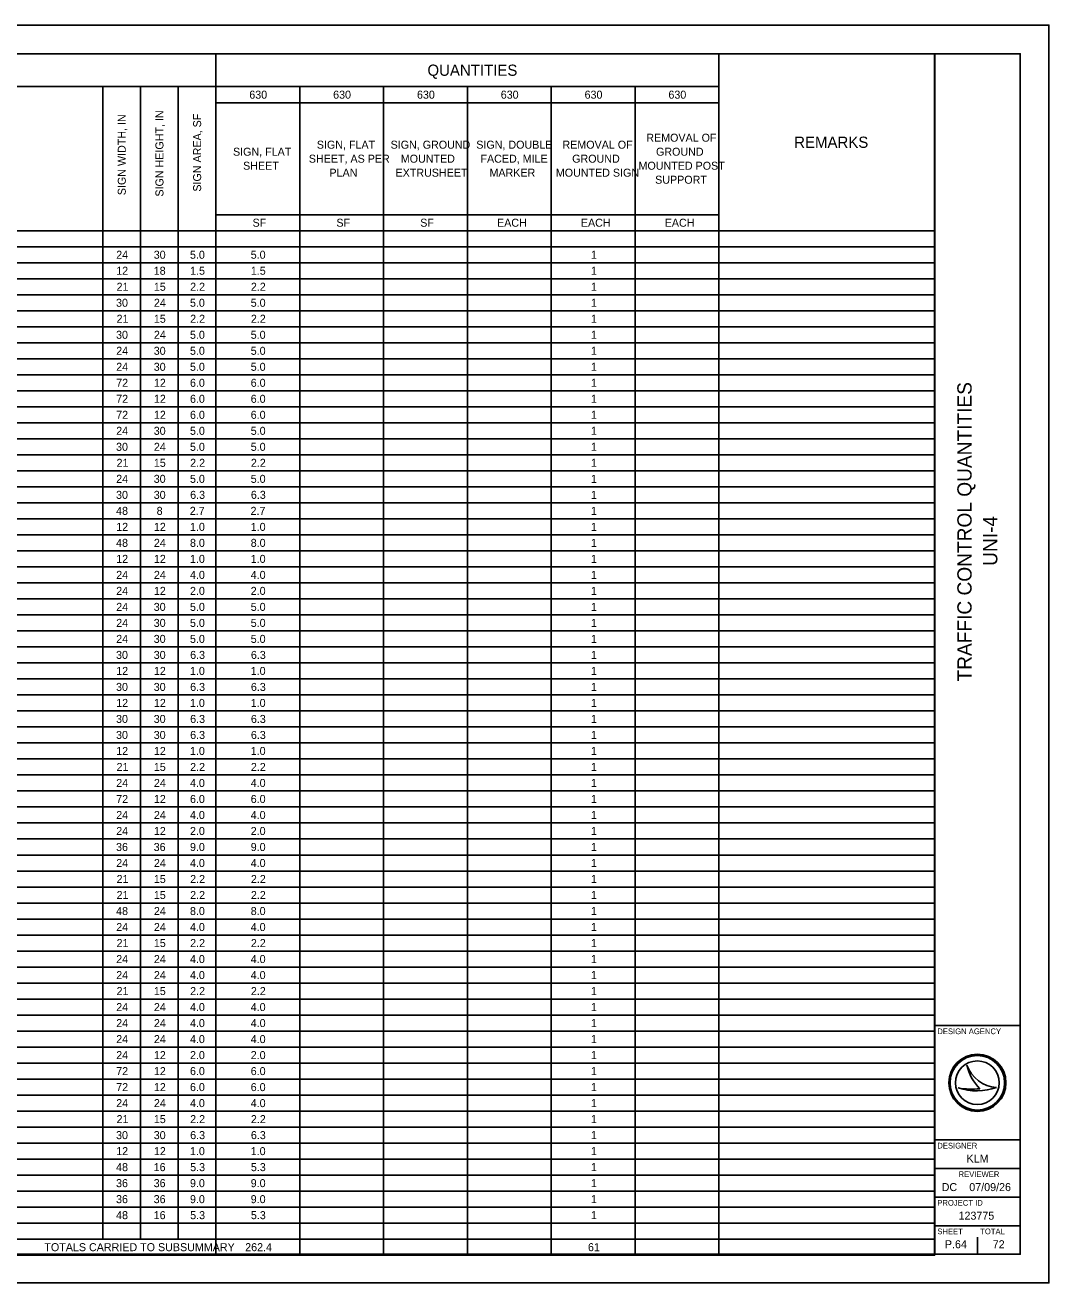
# Model space of a CAD drawing. Extents: x 0 to 34, y 0 to 22.
# Drawn here: x 16.1 to 34, y 0 to 22 of the extents above; entities that cross this region are included whole.
import ezdxf

# ---------------------------------------------------------------- set-up
doc = ezdxf.new("R2010")
doc.units = 0
for name, color, linetype in [('SH_Border', 7, 'Continuous'), ('SH_Cut_Line', 7, 'Continuous'), ('SH_Data', 7, 'Continuous'), ('SH_Text', 7, 'Continuous')]:
    doc.layers.add(name, color=color, linetype=linetype)

msp = doc.modelspace()

# ---------------------------------------------------------------- linework, layer by layer
at = {"layer": 'SH_Border'}
for p, q in [((32, 0.5), (32, 21.5)), ((32, 4.5), (33.5, 4.5)), ((32, 2.5), (33.5, 2.5)), ((32, 2), (33.5, 2)), ((32, 1.5), (33.5, 1.5)), ((32, 1), (33.5, 1))]:
    msp.add_line(p, q, dxfattribs=at)
msp.add_lwpolyline([(1.5, 21.5), (33.5, 21.5), (33.5, 0.5), (1.5, 0.5)], close=True, dxfattribs=at)
at = {"layer": 'SH_Cut_Line'}
msp.add_lwpolyline([(0, 0), (34, 0), (34, 22), (0, 22)], close=True, dxfattribs=at)
at = {"layer": 'SH_Data'}
for p, q in [((1.5, 21.5), (32.004, 21.5)), ((19.436, 21.5), (19.436, 0.484)), ((28.232, 21.5), (28.232, 0.484)), ((32.004, 21.5), (32.004, 0.484)), ((1.5, 20.924), (28.232, 20.924)), ((17.46, 20.924), (17.46, 0.764)), ((18.119, 20.924), (18.119, 0.764)), ((18.778, 20.924), (18.778, 0.764)), ((20.902, 20.924), (20.902, 0.484)), ((22.368, 20.924), (22.368, 0.484)), ((23.834, 20.924), (23.834, 0.484)), ((25.3, 20.924), (25.3, 0.484)), ((26.766, 20.924), (26.766, 0.484)), ((19.436, 20.644), (28.232, 20.644)), ((19.436, 18.684), (28.232, 18.684)), ((1.5, 18.404), (32.004, 18.404)), ((1.5, 18.124), (32.004, 18.124)), ((1.5, 17.844), (32.004, 17.844)), ((1.5, 17.564), (32.004, 17.564)), ((1.5, 17.284), (32.004, 17.284)), ((1.5, 17.004), (32.004, 17.004)), ((1.5, 16.724), (32.004, 16.724)), ((1.5, 16.444), (32.004, 16.444)), ((1.5, 16.164), (32.004, 16.164)), ((1.5, 15.884), (32.004, 15.884)), ((1.5, 15.604), (32.004, 15.604)), ((1.5, 15.324), (32.004, 15.324)), ((1.5, 15.044), (32.004, 15.044)), ((1.5, 14.764), (32.004, 14.764)), ((1.5, 14.484), (32.004, 14.484)), ((1.5, 14.204), (32.004, 14.204)), ((1.5, 13.924), (32.004, 13.924)), ((1.5, 13.644), (32.004, 13.644)), ((1.5, 13.364), (32.004, 13.364)), ((1.5, 13.084), (32.004, 13.084)), ((1.5, 12.804), (32.004, 12.804)), ((1.5, 12.524), (32.004, 12.524)), ((1.5, 12.244), (32.004, 12.244)), ((1.5, 11.964), (32.004, 11.964)), ((1.5, 11.684), (32.004, 11.684)), ((1.5, 11.404), (32.004, 11.404)), ((1.5, 11.124), (32.004, 11.124)), ((1.5, 10.844), (32.004, 10.844)), ((1.5, 10.564), (32.004, 10.564)), ((1.5, 10.284), (32.004, 10.284)), ((1.5, 10.004), (32.004, 10.004)), ((1.5, 9.724), (32.004, 9.724)), ((1.5, 9.444), (32.004, 9.444)), ((1.5, 9.164), (32.004, 9.164)), ((1.5, 8.884), (32.004, 8.884)), ((1.5, 8.604), (32.004, 8.604)), ((1.5, 8.324), (32.004, 8.324)), ((1.5, 8.044), (32.004, 8.044)), ((1.5, 7.764), (32.004, 7.764)), ((1.5, 7.484), (32.004, 7.484)), ((1.5, 7.204), (32.004, 7.204)), ((1.5, 6.924), (32.004, 6.924)), ((1.5, 6.644), (32.004, 6.644)), ((1.5, 6.364), (32.004, 6.364)), ((1.5, 6.084), (32.004, 6.084)), ((1.5, 5.804), (32.004, 5.804)), ((1.5, 5.524), (32.004, 5.524)), ((1.5, 5.244), (32.004, 5.244)), ((1.5, 4.964), (32.004, 4.964)), ((1.5, 4.684), (32.004, 4.684)), ((1.5, 4.404), (32.004, 4.404)), ((1.5, 4.124), (32.004, 4.124)), ((1.5, 3.844), (32.004, 3.844)), ((32.567, 3.81), (32.567, 3.81)), ((1.5, 3.564), (32.004, 3.564)), ((32.417, 3.41), (32.417, 3.41)), ((32.75, 3.5), (32.75, 3.5)), ((33.087, 3.419), (33.087, 3.419)), ((1.5, 3.284), (32.004, 3.284)), ((1.5, 3.004), (32.004, 3.004)), ((1.5, 2.724), (32.004, 2.724)), ((1.5, 2.444), (32.004, 2.444)), ((1.5, 2.164), (32.004, 2.164)), ((1.5, 1.884), (32.004, 1.884)), ((1.5, 1.604), (32.004, 1.604)), ((1.5, 1.324), (32.004, 1.324)), ((1.5, 1.044), (32.004, 1.044)), ((1.5, 0.764), (32.004, 0.764)), ((32.375, 0.675), (32.375, 0.675)), ((32.75, 0.5), (32.75, 0.8)), ((1.5, 0.484), (32.004, 0.484))]:
    msp.add_line(p, q, dxfattribs=at)
for radius in [0.5, 0.477, 0.477, 0.382]:
    msp.add_circle((32.75, 3.5), radius, dxfattribs=at)
for centre, radius, start, end in [((33.116, 3.998), 0.58, 198.9257, 198.9319), ((33.347, 3.97), 0.796, 191.6379, 191.6421), ((33.116, 3.998), 0.58, 198.9319, 267.1657), ((33.347, 3.97), 0.796, 191.6421, 226.0947), ((32.739, 4.37), 1.013, 251.4576, 290.0832), ((32.648, 4.654), 1.266, 259.4964, 259.4995), ((32.739, 4.37), 1.013, 251.4527, 251.4576), ((32.648, 4.654), 1.266, 259.4995, 276.6672)]:
    msp.add_arc(centre, radius, start, end, dxfattribs=at)

# ---------------------------------------------------------------- texts
for s, p in [('TRAFFIC CONTROL QUANTITIES', (32.65, 10.519)), ('UNI-4', (33.1, 12.542))]:
    msp.add_text(s, height=0.25, rotation=90, dxfattribs=at).set_placement(p)
for s, height, p in [('DESIGN AGENCY', 0.1, (32.05, 4.35)), ('DESIGNER', 0.1, (32.05, 2.35)), ('KLM', 0.14, (32.561, 2.105)), ('REVIEWER', 0.1, (32.422, 1.85)), ('DC', 0.14, (32.126, 1.605)), ('07/09/26', 0.14, (32.609, 1.605)), ('PROJECT ID', 0.1, (32.05, 1.35)), ('123775', 0.14, (32.421, 1.105)), ('SHEET', 0.1, (32.05, 0.85)), ('TOTAL', 0.1, (32.8, 0.85)), ('P.64', 0.14, (32.182, 0.605)), ('72', 0.14, (33.019, 0.605))]:
    msp.add_text(s, height=height, dxfattribs=at).set_placement(p)
at = {"layer": 'SH_Text'}
for s, height, p in [('QUANTITIES', 0.196, (23.134, 21.114)), ('630', 0.14, (20.019, 20.714)), ('630', 0.14, (21.485, 20.714)), ('630', 0.14, (22.951, 20.714)), ('630', 0.14, (24.416, 20.714)), ('630', 0.14, (25.882, 20.714)), ('630', 0.14, (27.348, 20.714)), ('REMOVAL OF ', 0.14, (26.961, 19.961)), ('REMARKS', 0.196, (29.547, 19.854)), ('SIGN, FLAT ', 0.14, (19.734, 19.716)), ('SIGN, FLAT ', 0.14, (21.2, 19.839)), ('SIGN, GROUND ', 0.14, (22.49, 19.839)), ('SIGN, DOUBLE ', 0.14, (23.988, 19.839)), ('REMOVAL OF ', 0.14, (25.495, 19.839)), ('GROUND ', 0.14, (27.131, 19.716)), ('SHEET', 0.14, (19.911, 19.471)), ('SHEET, AS PER ', 0.14, (21.06, 19.594)), ('MOUNTED ', 0.14, (22.668, 19.594)), ('FACED, MILE ', 0.14, (24.061, 19.594)), ('GROUND ', 0.14, (25.665, 19.594)), ('MOUNTED POST ', 0.14, (26.825, 19.471)), ('PLAN', 0.14, (21.421, 19.349)), ('EXTRUSHEET', 0.14, (22.576, 19.349)), ('MARKER', 0.14, (24.219, 19.349)), ('MOUNTED SIGN', 0.14, (25.379, 19.349)), ('SUPPORT', 0.14, (27.116, 19.226)), ('SF', 0.14, (20.076, 18.474)), ('SF', 0.14, (21.542, 18.474)), ('SF', 0.14, (23.008, 18.474)), ('EACH', 0.14, (24.351, 18.474)), ('EACH', 0.14, (25.817, 18.474)), ('EACH', 0.14, (27.283, 18.474)), ('24', 0.14, (17.692, 17.914)), ('30', 0.14, (18.348, 17.914)), ('5.0', 0.14, (18.982, 17.914)), ('5.0', 0.14, (20.044, 17.914)), ('1', 0.14, (25.992, 17.914)), ('12', 0.14, (17.692, 17.634)), ('18', 0.14, (18.348, 17.634)), ('1.5', 0.14, (18.984, 17.634)), ('1.5', 0.14, (20.046, 17.634)), ('1', 0.14, (25.992, 17.634)), ('21', 0.14, (17.698, 17.354)), ('15', 0.14, (18.35, 17.354)), ('2.2', 0.14, (18.985, 17.354)), ('2.2', 0.14, (20.047, 17.354)), ('1', 0.14, (25.992, 17.354)), ('30', 0.14, (17.689, 17.074)), ('24', 0.14, (18.351, 17.074)), ('5.0', 0.14, (18.982, 17.074)), ('5.0', 0.14, (20.044, 17.074)), ('1', 0.14, (25.992, 17.074)), ('21', 0.14, (17.698, 16.794)), ('15', 0.14, (18.35, 16.794)), ('2.2', 0.14, (18.985, 16.794)), ('2.2', 0.14, (20.047, 16.794)), ('1', 0.14, (25.992, 16.794)), ('30', 0.14, (17.689, 16.514)), ('24', 0.14, (18.351, 16.514)), ('5.0', 0.14, (18.982, 16.514)), ('5.0', 0.14, (20.044, 16.514)), ('1', 0.14, (25.992, 16.514)), ('24', 0.14, (17.692, 16.234)), ('30', 0.14, (18.348, 16.234)), ('5.0', 0.14, (18.982, 16.234)), ('5.0', 0.14, (20.044, 16.234)), ('1', 0.14, (25.992, 16.234)), ('24', 0.14, (17.692, 15.954)), ('30', 0.14, (18.348, 15.954)), ('5.0', 0.14, (18.982, 15.954)), ('5.0', 0.14, (20.044, 15.954)), ('1', 0.14, (25.992, 15.954)), ('72', 0.14, (17.692, 15.674)), ('12', 0.14, (18.351, 15.674)), ('6.0', 0.14, (18.982, 15.674)), ('6.0', 0.14, (20.044, 15.674)), ('1', 0.14, (25.992, 15.674)), ('72', 0.14, (17.692, 15.394)), ('12', 0.14, (18.351, 15.394)), ('6.0', 0.14, (18.982, 15.394)), ('6.0', 0.14, (20.044, 15.394)), ('1', 0.14, (25.992, 15.394)), ('72', 0.14, (17.692, 15.114)), ('12', 0.14, (18.351, 15.114)), ('6.0', 0.14, (18.982, 15.114)), ('6.0', 0.14, (20.044, 15.114)), ('1', 0.14, (25.992, 15.114)), ('24', 0.14, (17.692, 14.834)), ('30', 0.14, (18.348, 14.834)), ('5.0', 0.14, (18.982, 14.834)), ('5.0', 0.14, (20.044, 14.834)), ('1', 0.14, (25.992, 14.834)), ('30', 0.14, (17.689, 14.554)), ('24', 0.14, (18.351, 14.554)), ('5.0', 0.14, (18.982, 14.554)), ('5.0', 0.14, (20.044, 14.554)), ('1', 0.14, (25.992, 14.554)), ('21', 0.14, (17.698, 14.274)), ('15', 0.14, (18.35, 14.274)), ('2.2', 0.14, (18.985, 14.274)), ('2.2', 0.14, (20.047, 14.274)), ('1', 0.14, (25.992, 14.274)), ('24', 0.14, (17.692, 13.994)), ('30', 0.14, (18.348, 13.994)), ('5.0', 0.14, (18.982, 13.994)), ('5.0', 0.14, (20.044, 13.994)), ('1', 0.14, (25.992, 13.994)), ('30', 0.14, (17.689, 13.714)), ('30', 0.14, (18.348, 13.714)), ('6.3', 0.14, (18.985, 13.714)), ('6.3', 0.14, (20.047, 13.714)), ('1', 0.14, (25.992, 13.714)), ('48', 0.14, (17.69, 13.434)), ('8', 0.14, (18.399, 13.434)), ('2.7', 0.14, (18.979, 13.434)), ('2.7', 0.14, (20.041, 13.434)), ('1', 0.14, (25.992, 13.434)), ('12', 0.14, (17.692, 13.154)), ('12', 0.14, (18.351, 13.154)), ('1.0', 0.14, (18.982, 13.154)), ('1.0', 0.14, (20.044, 13.154)), ('1', 0.14, (25.992, 13.154)), ('48', 0.14, (17.69, 12.874)), ('24', 0.14, (18.351, 12.874)), ('8.0', 0.14, (18.982, 12.874)), ('8.0', 0.14, (20.044, 12.874)), ('1', 0.14, (25.992, 12.874)), ('12', 0.14, (17.692, 12.594)), ('12', 0.14, (18.351, 12.594)), ('1.0', 0.14, (18.982, 12.594)), ('1.0', 0.14, (20.044, 12.594)), ('1', 0.14, (25.992, 12.594)), ('24', 0.14, (17.692, 12.314)), ('24', 0.14, (18.351, 12.314)), ('4.0', 0.14, (18.982, 12.314)), ('4.0', 0.14, (20.044, 12.314)), ('1', 0.14, (25.992, 12.314)), ('24', 0.14, (17.692, 12.034)), ('12', 0.14, (18.351, 12.034)), ('2.0', 0.14, (18.982, 12.034)), ('2.0', 0.14, (20.044, 12.034)), ('1', 0.14, (25.992, 12.034)), ('24', 0.14, (17.692, 11.754)), ('30', 0.14, (18.348, 11.754)), ('5.0', 0.14, (18.982, 11.754)), ('5.0', 0.14, (20.044, 11.754)), ('1', 0.14, (25.992, 11.754)), ('24', 0.14, (17.692, 11.474)), ('30', 0.14, (18.348, 11.474)), ('5.0', 0.14, (18.982, 11.474)), ('5.0', 0.14, (20.044, 11.474)), ('1', 0.14, (25.992, 11.474)), ('24', 0.14, (17.692, 11.194)), ('30', 0.14, (18.348, 11.194)), ('5.0', 0.14, (18.982, 11.194)), ('5.0', 0.14, (20.044, 11.194)), ('1', 0.14, (25.992, 11.194)), ('30', 0.14, (17.689, 10.914)), ('30', 0.14, (18.348, 10.914)), ('6.3', 0.14, (18.985, 10.914)), ('6.3', 0.14, (20.047, 10.914)), ('1', 0.14, (25.992, 10.914)), ('12', 0.14, (17.692, 10.634)), ('12', 0.14, (18.351, 10.634)), ('1.0', 0.14, (18.982, 10.634)), ('1.0', 0.14, (20.044, 10.634)), ('1', 0.14, (25.992, 10.634)), ('30', 0.14, (17.689, 10.354)), ('30', 0.14, (18.348, 10.354)), ('6.3', 0.14, (18.985, 10.354)), ('6.3', 0.14, (20.047, 10.354)), ('1', 0.14, (25.992, 10.354)), ('12', 0.14, (17.692, 10.074)), ('12', 0.14, (18.351, 10.074)), ('1.0', 0.14, (18.982, 10.074)), ('1.0', 0.14, (20.044, 10.074)), ('1', 0.14, (25.992, 10.074)), ('30', 0.14, (17.689, 9.794)), ('30', 0.14, (18.348, 9.794)), ('6.3', 0.14, (18.985, 9.794)), ('6.3', 0.14, (20.047, 9.794)), ('1', 0.14, (25.992, 9.794)), ('30', 0.14, (17.689, 9.514)), ('30', 0.14, (18.348, 9.514)), ('6.3', 0.14, (18.985, 9.514)), ('6.3', 0.14, (20.047, 9.514)), ('1', 0.14, (25.992, 9.514)), ('12', 0.14, (17.692, 9.234)), ('12', 0.14, (18.351, 9.234)), ('1.0', 0.14, (18.982, 9.234)), ('1.0', 0.14, (20.044, 9.234)), ('1', 0.14, (25.992, 9.234)), ('21', 0.14, (17.698, 8.954)), ('15', 0.14, (18.35, 8.954)), ('2.2', 0.14, (18.985, 8.954)), ('2.2', 0.14, (20.047, 8.954)), ('1', 0.14, (25.992, 8.954)), ('24', 0.14, (17.692, 8.674)), ('24', 0.14, (18.351, 8.674)), ('4.0', 0.14, (18.982, 8.674)), ('4.0', 0.14, (20.044, 8.674)), ('1', 0.14, (25.992, 8.674)), ('72', 0.14, (17.692, 8.394)), ('12', 0.14, (18.351, 8.394)), ('6.0', 0.14, (18.982, 8.394)), ('6.0', 0.14, (20.044, 8.394)), ('1', 0.14, (25.992, 8.394)), ('24', 0.14, (17.692, 8.114)), ('24', 0.14, (18.351, 8.114)), ('4.0', 0.14, (18.982, 8.114)), ('4.0', 0.14, (20.044, 8.114)), ('1', 0.14, (25.992, 8.114)), ('24', 0.14, (17.692, 7.834)), ('12', 0.14, (18.351, 7.834)), ('2.0', 0.14, (18.982, 7.834)), ('2.0', 0.14, (20.044, 7.834)), ('1', 0.14, (25.992, 7.834)), ('36', 0.14, (17.689, 7.554)), ('36', 0.14, (18.347, 7.554)), ('9.0', 0.14, (18.982, 7.554)), ('9.0', 0.14, (20.044, 7.554)), ('1', 0.14, (25.992, 7.554)), ('24', 0.14, (17.692, 7.274)), ('24', 0.14, (18.351, 7.274)), ('4.0', 0.14, (18.982, 7.274)), ('4.0', 0.14, (20.044, 7.274)), ('1', 0.14, (25.992, 7.274)), ('21', 0.14, (17.698, 6.994)), ('15', 0.14, (18.35, 6.994)), ('2.2', 0.14, (18.985, 6.994)), ('2.2', 0.14, (20.047, 6.994)), ('1', 0.14, (25.992, 6.994)), ('21', 0.14, (17.698, 6.714)), ('15', 0.14, (18.35, 6.714)), ('2.2', 0.14, (18.985, 6.714)), ('2.2', 0.14, (20.047, 6.714)), ('1', 0.14, (25.992, 6.714)), ('48', 0.14, (17.69, 6.434)), ('24', 0.14, (18.351, 6.434)), ('8.0', 0.14, (18.982, 6.434)), ('8.0', 0.14, (20.044, 6.434)), ('1', 0.14, (25.992, 6.434)), ('24', 0.14, (17.692, 6.154)), ('24', 0.14, (18.351, 6.154)), ('4.0', 0.14, (18.982, 6.154)), ('4.0', 0.14, (20.044, 6.154)), ('1', 0.14, (25.992, 6.154)), ('21', 0.14, (17.698, 5.874)), ('15', 0.14, (18.35, 5.874)), ('2.2', 0.14, (18.985, 5.874)), ('2.2', 0.14, (20.047, 5.874)), ('1', 0.14, (25.992, 5.874)), ('24', 0.14, (17.692, 5.594)), ('24', 0.14, (18.351, 5.594)), ('4.0', 0.14, (18.982, 5.594)), ('4.0', 0.14, (20.044, 5.594)), ('1', 0.14, (25.992, 5.594)), ('24', 0.14, (17.692, 5.314)), ('24', 0.14, (18.351, 5.314)), ('4.0', 0.14, (18.982, 5.314)), ('4.0', 0.14, (20.044, 5.314)), ('1', 0.14, (25.992, 5.314)), ('21', 0.14, (17.698, 5.034)), ('15', 0.14, (18.35, 5.034)), ('2.2', 0.14, (18.985, 5.034)), ('2.2', 0.14, (20.047, 5.034)), ('1', 0.14, (25.992, 5.034)), ('24', 0.14, (17.692, 4.754)), ('24', 0.14, (18.351, 4.754)), ('4.0', 0.14, (18.982, 4.754)), ('4.0', 0.14, (20.044, 4.754)), ('1', 0.14, (25.992, 4.754)), ('24', 0.14, (17.692, 4.474)), ('24', 0.14, (18.351, 4.474)), ('4.0', 0.14, (18.982, 4.474)), ('4.0', 0.14, (20.044, 4.474)), ('1', 0.14, (25.992, 4.474)), ('24', 0.14, (17.692, 4.194)), ('24', 0.14, (18.351, 4.194)), ('4.0', 0.14, (18.982, 4.194)), ('4.0', 0.14, (20.044, 4.194)), ('1', 0.14, (25.992, 4.194)), ('24', 0.14, (17.692, 3.914)), ('12', 0.14, (18.351, 3.914)), ('2.0', 0.14, (18.982, 3.914)), ('2.0', 0.14, (20.044, 3.914)), ('1', 0.14, (25.992, 3.914)), ('72', 0.14, (17.692, 3.634)), ('12', 0.14, (18.351, 3.634)), ('6.0', 0.14, (18.982, 3.634)), ('6.0', 0.14, (20.044, 3.634)), ('1', 0.14, (25.992, 3.634)), ('72', 0.14, (17.692, 3.354)), ('12', 0.14, (18.351, 3.354)), ('6.0', 0.14, (18.982, 3.354)), ('6.0', 0.14, (20.044, 3.354)), ('1', 0.14, (25.992, 3.354)), ('24', 0.14, (17.692, 3.074)), ('24', 0.14, (18.351, 3.074)), ('4.0', 0.14, (18.982, 3.074)), ('4.0', 0.14, (20.044, 3.074)), ('1', 0.14, (25.992, 3.074)), ('21', 0.14, (17.698, 2.794)), ('15', 0.14, (18.35, 2.794)), ('2.2', 0.14, (18.985, 2.794)), ('2.2', 0.14, (20.047, 2.794)), ('1', 0.14, (25.992, 2.794)), ('30', 0.14, (17.689, 2.514)), ('30', 0.14, (18.348, 2.514)), ('6.3', 0.14, (18.985, 2.514)), ('6.3', 0.14, (20.047, 2.514)), ('1', 0.14, (25.992, 2.514)), ('12', 0.14, (17.692, 2.234)), ('12', 0.14, (18.351, 2.234)), ('1.0', 0.14, (18.982, 2.234)), ('1.0', 0.14, (20.044, 2.234)), ('1', 0.14, (25.992, 2.234)), ('48', 0.14, (17.69, 1.954)), ('16', 0.14, (18.347, 1.954)), ('5.3', 0.14, (18.985, 1.954)), ('5.3', 0.14, (20.047, 1.954)), ('1', 0.14, (25.992, 1.954)), ('36', 0.14, (17.689, 1.674)), ('36', 0.14, (18.347, 1.674)), ('9.0', 0.14, (18.982, 1.674)), ('9.0', 0.14, (20.044, 1.674)), ('1', 0.14, (25.992, 1.674)), ('36', 0.14, (17.689, 1.394)), ('36', 0.14, (18.347, 1.394)), ('9.0', 0.14, (18.982, 1.394)), ('9.0', 0.14, (20.044, 1.394)), ('1', 0.14, (25.992, 1.394)), ('48', 0.14, (17.69, 1.114)), ('16', 0.14, (18.347, 1.114)), ('5.3', 0.14, (18.985, 1.114)), ('5.3', 0.14, (20.047, 1.114)), ('1', 0.14, (25.992, 1.114)), ('TOTALS CARRIED TO SUBSUMMARY', 0.14, (16.436, 0.554)), ('262.4', 0.14, (19.947, 0.554)), ('61', 0.14, (25.941, 0.554))]:
    msp.add_text(s, height=height, dxfattribs=at).set_placement(p)
for s, p in [('SIGN HEIGHT, IN', (18.518, 19.001)), ('SIGN WIDTH, IN', (17.859, 19.026)), ('SIGN AREA, SF', (19.177, 19.088))]:
    msp.add_text(s, height=0.14, rotation=90, dxfattribs=at).set_placement(p)

doc.saveas('drawing.dxf')
